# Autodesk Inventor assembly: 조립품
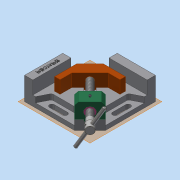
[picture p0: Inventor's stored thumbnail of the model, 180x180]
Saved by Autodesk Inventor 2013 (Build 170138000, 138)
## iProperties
Created: 2019-04
Part Number: 조립품
Document SubType Name: Assembly
Designer: dgall
Author: dgall
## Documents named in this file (11)
- C:\Users\dgall\Desktop\490407V1002\조립품.iam
- C:\Users\dgall\Desktop\490407V1002\본체.ipt
- C:\Users\dgall\Desktop\490407V1002\리드스크류.ipt
- C:\Users\dgall\Desktop\490407V1002\멈춤나사 M4x5.ipt
- C:\Users\dgall\Desktop\490407V1002\멈춤나사 M4x10.ipt
- C:\Users\dgall\Desktop\490407V1002\볼트 M4x16.ipt
- C:\Users\dgall\Desktop\490407V1002\부시.ipt
- C:\Users\dgall\Desktop\490407V1002\서포트.ipt
- C:\Users\dgall\Desktop\490407V1002\조.ipt
- C:\Users\dgall\Desktop\490407V1002\평행 핀 2.5x24.ipt
- C:\Users\dgall\Desktop\490407V1002\핸들.ipt
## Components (1 placed, 1 different names)
1. 핸들:1
